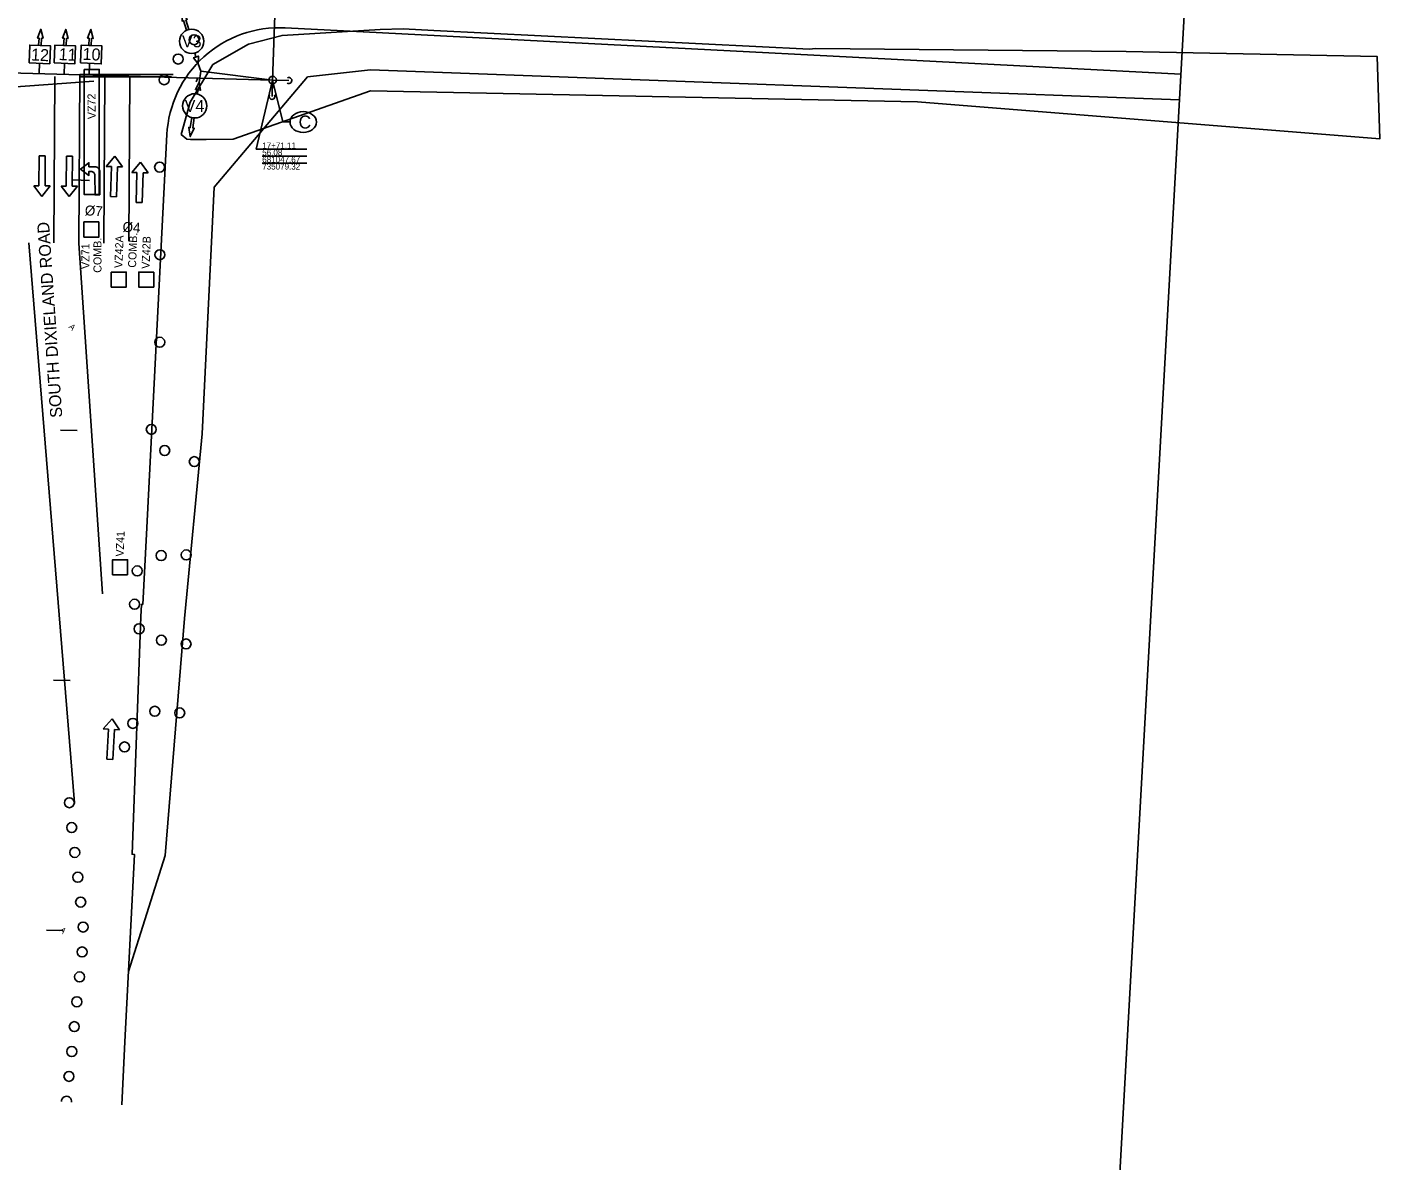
# Model space of a CAD drawing. Extents: x 679444 to 687671, y 733868 to 736107.
# Drawn here: x 680949 to 681490, y 734647 to 735101 of the extents above; entities that cross this region are included whole.
import ezdxf

# ---------------------------------------------------------------- set-up
doc = ezdxf.new("R2010")
doc.units = 0
for name, color, linetype in [('$', 7, 'Continuous'), ('090338 Base_Design base 1-1 - R_Horz Alg', 7, 'Continuous'), ('border All Plan 20-40_Border 1 - Level 1', 7, 'Continuous'), ('Clipping Boundary', 7, 'Continuous'), ('MOT Stage 1', 7, 'Continuous'), ('MOT Stage 1 Lanes', 7, 'Continuous'), ('R_Horz Alg Annot', 7, 'Continuous'), ('R_Horz Alg Station', 7, 'Continuous'), ('RW-EX', 7, 'Continuous'), ('RW-PR', 7, 'Continuous'), ('SIGNAL-EX', 7, 'Continuous'), ('SIGNAL-PLAN VIEW LABLES', 7, 'Continuous'), ('TITEXT', 7, 'Continuous'), ('Video-Zones-pr', 7, 'Continuous')]:
    doc.layers.add(name, color=color, linetype=linetype)

# ---------------------------------------------------------------- blocks, each defined once
blk = doc.blocks.new('BAREL_1514')
at = {"layer": 'MOT Stage 1'}
blk.add_circle((-0.01, 0), 2, dxfattribs=at)
blk = doc.blocks.new('BAREL_1515')
at = {"layer": 'MOT Stage 1'}
blk.add_circle((-0.01, 0), 2, dxfattribs=at)
blk = doc.blocks.new('BAREL_1516')
at = {"layer": 'MOT Stage 1'}
blk.add_circle((-0.01, 0), 2, dxfattribs=at)
blk = doc.blocks.new('BAREL_1517')
at = {"layer": 'MOT Stage 1'}
blk.add_circle((-0.01, 0), 2, dxfattribs=at)
blk = doc.blocks.new('BAREL_1518')
at = {"layer": 'MOT Stage 1'}
blk.add_circle((-0.01, 0), 2, dxfattribs=at)
blk = doc.blocks.new('BAREL_1520')
at = {"layer": 'MOT Stage 1'}
blk.add_circle((0, -0.01), 2, dxfattribs=at)
blk = doc.blocks.new('BAREL_1521')
at = {"layer": 'MOT Stage 1'}
blk.add_circle((0, -0.01), 2, dxfattribs=at)
blk = doc.blocks.new('BAREL_1522')
at = {"layer": 'MOT Stage 1'}
blk.add_circle((0, -0.01), 2, dxfattribs=at)
blk = doc.blocks.new('BAREL_1523')
at = {"layer": 'MOT Stage 1'}
blk.add_circle((0, -0.01), 2, dxfattribs=at)
blk = doc.blocks.new('SARROW_172')
at = {"layer": 'MOT Stage 1'}
for p, q in [((0, 0), (-6, 0)), ((0, -29.4), (0, 0)), ((-6, -29.4), (-6, 0)), ((-6, -29.4), (-11, -29.4)), ((-3, -39.8), (-11, -29.4)), ((5, -29.4), (-3, -39.8)), ((5, -29.4), (0, -29.4))]:
    blk.add_line(p, q, dxfattribs=at)
blk = doc.blocks.new('SARROW_177')
at = {"layer": 'MOT Stage 1'}
for p, q in [((0, 0), (-6, 0)), ((0, -29.4), (0, 0)), ((-6, -29.4), (-6, 0)), ((-6, -29.4), (-11, -29.4)), ((-3, -39.8), (-11, -29.4)), ((5, -29.4), (-3, -39.8)), ((5, -29.4), (0, -29.4))]:
    blk.add_line(p, q, dxfattribs=at)
blk = doc.blocks.new('SARROW_182')
at = {"layer": 'MOT Stage 1'}
for p, q in [((0, 0), (-6, 0)), ((0, -29.4), (0, 0)), ((-6, -29.4), (-6, 0)), ((-6, -29.4), (-11, -29.4)), ((-3, -39.8), (-11, -29.4)), ((5, -29.4), (-3, -39.8)), ((5, -29.4), (0, -29.4))]:
    blk.add_line(p, q, dxfattribs=at)
blk = doc.blocks.new('BAREL_1564')
at = {"layer": 'MOT Stage 1'}
blk.add_circle((0, -0.01), 2, dxfattribs=at)
blk = doc.blocks.new('BAREL_1565')
at = {"layer": 'MOT Stage 1'}
blk.add_circle((0, -0.01), 2, dxfattribs=at)
blk = doc.blocks.new('BAREL_1566')
at = {"layer": 'MOT Stage 1'}
blk.add_circle((0, -0.01), 2, dxfattribs=at)
blk = doc.blocks.new('BAREL_1567')
at = {"layer": 'MOT Stage 1'}
blk.add_circle((0, -0.01), 2, dxfattribs=at)
blk = doc.blocks.new('BAREL_1568')
at = {"layer": 'MOT Stage 1'}
blk.add_circle((-0.01, 0), 2, dxfattribs=at)
blk = doc.blocks.new('BAREL_1569')
at = {"layer": 'MOT Stage 1'}
blk.add_circle((-0.01, 0), 2, dxfattribs=at)
blk = doc.blocks.new('BAREL_1570')
at = {"layer": 'MOT Stage 1'}
blk.add_circle((-0.01, 0), 2, dxfattribs=at)
blk = doc.blocks.new('BAREL_1571')
at = {"layer": 'MOT Stage 1'}
blk.add_circle((-0.01, 0), 2, dxfattribs=at)
blk = doc.blocks.new('BAREL_1572')
at = {"layer": 'MOT Stage 1'}
blk.add_circle((-0.01, 0), 2, dxfattribs=at)
blk = doc.blocks.new('BAREL_1573')
at = {"layer": 'MOT Stage 1'}
blk.add_circle((-0.01, 0), 2, dxfattribs=at)
blk = doc.blocks.new('BAREL_1574')
at = {"layer": 'MOT Stage 1'}
blk.add_circle((-0.01, 0), 2, dxfattribs=at)
blk = doc.blocks.new('SARROW_185')
at = {"layer": 'MOT Stage 1'}
for p, q in [((0, 0), (-6, 0)), ((0, -29.4), (0, 0)), ((-6, -29.4), (-6, 0)), ((-6, -29.4), (-11, -29.4)), ((-3, -39.8), (-11, -29.4)), ((5, -29.4), (-3, -39.8)), ((5, -29.4), (0, -29.4))]:
    blk.add_line(p, q, dxfattribs=at)
blk = doc.blocks.new('BAREL_1583')
at = {"layer": 'MOT Stage 1'}
blk.add_circle((-0.01, 0), 2, dxfattribs=at)
blk = doc.blocks.new('BAREL_1584')
at = {"layer": 'MOT Stage 1'}
blk.add_circle((-0.01, 0), 2, dxfattribs=at)
blk = doc.blocks.new('BAREL_1585')
at = {"layer": 'MOT Stage 1'}
blk.add_circle((-0.01, 0), 2, dxfattribs=at)
blk = doc.blocks.new('BAREL_1586')
at = {"layer": 'MOT Stage 1'}
blk.add_circle((-0.01, 0), 2, dxfattribs=at)
blk = doc.blocks.new('BAREL_1587')
at = {"layer": 'MOT Stage 1'}
blk.add_circle((-0.01, 0), 2, dxfattribs=at)
blk = doc.blocks.new('BAREL_1588')
at = {"layer": 'MOT Stage 1'}
blk.add_circle((-0.01, 0), 2, dxfattribs=at)
blk = doc.blocks.new('BAREL_1589')
at = {"layer": 'MOT Stage 1'}
blk.add_circle((-0.01, 0), 2, dxfattribs=at)
blk = doc.blocks.new('BAREL_1590')
at = {"layer": 'MOT Stage 1'}
blk.add_circle((-0.01, 0), 2, dxfattribs=at)
blk = doc.blocks.new('BAREL_1591')
at = {"layer": 'MOT Stage 1'}
blk.add_circle((-0.01, 0), 2, dxfattribs=at)
blk = doc.blocks.new('BAREL_1592')
at = {"layer": 'MOT Stage 1'}
blk.add_circle((-0.01, 0), 2, dxfattribs=at)
blk = doc.blocks.new('BAREL_1593')
at = {"layer": 'MOT Stage 1'}
blk.add_circle((-0.01, 0), 2, dxfattribs=at)
blk = doc.blocks.new('BAREL_1594')
at = {"layer": 'MOT Stage 1'}
blk.add_circle((-0.01, 0), 2, dxfattribs=at)
blk = doc.blocks.new('SARROW_186')
at = {"layer": 'MOT Stage 1'}
for p, q in [((-6, -29.4), (-6, 0)), ((0, 0), (-6, 0)), ((0, -29.4), (0, 0)), ((-6, -29.4), (-11, -29.4)), ((-3, -39.8), (-11, -29.4)), ((5, -29.4), (-3, -39.8)), ((5, -29.4), (0, -29.4))]:
    blk.add_line(p, q, dxfattribs=at)
blk = doc.blocks.new('POINT_DISPLAY')
blk.add_line((0, 0), (0, 0))

msp = doc.modelspace()

# ---------------------------------------------------------------- linework, layer by layer
at = {"layer": '$'}
for p, q in [((681051.82, 735197.81), (681047.67, 735079.32)), ((681047.67, 735079.32), (680910.95, 735083.16))]:
    msp.add_line(p, q, dxfattribs=at)
for points in [[(681047.44, 735072.83), (681047.67, 735079.32)], [(681054.16, 735079.14), (681047.67, 735079.32)]]:
    msp.add_lwpolyline(points, dxfattribs=at)
for centre, start, end in [((681054.16, 735079.14), 238.3918, 118.3918), ((681047.44, 735072.83), 147.9937, 27.9937)]:
    msp.add_arc(centre, 1.2, start, end, dxfattribs=at)
at = {"layer": 'border All Plan 20-40_Border 1 - Level 1'}
msp.add_line((681384.1, 734599.57), (681440.93, 735625.3), dxfattribs=at)
at = {"layer": 'Clipping Boundary'}
msp.add_lwpolyline([(681013.37, 735055.78), (681014.86, 735055.61), (681021.06, 735055.55), (681031.94, 735055.66), (681086.85, 735075.03), (681305.56, 735070.63), (681490.46, 735055.86), (681489.41, 735088.76), (681389.02, 735090.81), (681264.81, 735091.94), (681262.37, 735091.76), (681112.19, 735099.16), (681099.83, 735099.77), (681090.68, 735099.5), (681051.46, 735097.19), (681038, 735093.68), (681023.75, 735085.5), (681014.67, 735070.5), (681011.14, 735057.59)], close=True, dxfattribs=at)
at = {"layer": 'MOT Stage 1'}
for points in [[(680976.62, 735044.72), (680976.94, 735044.72), (680974.21, 735044.7), (680974.2, 735046.29), (680970.92, 735043.73), (680974.23, 735041.21), (680974.22, 735042.8), (680975.05, 735042.81)], [(680976.65, 735041.23), (680976.7, 735033.43), (680978.61, 735033.45)], [(680978.61, 735033.45), (680978.54, 735043.15), (680978.54, 735042.83)]]:
    msp.add_lwpolyline(points, dxfattribs=at)
for centre, radius, start, end in [((680975.06, 735041.22), 1.59, 0.3996, 90.3996), ((680976.64, 735042.82), 1.9, 0.3996, 90.3996), ((680965.25, 734671.07), 2, 349.7483, 183.9093)]:
    msp.add_arc(centre, radius, start, end, dxfattribs=at)
at = {"layer": 'MOT Stage 1 Lanes'}
for p, q in [((680950.15, 735014.32), (680968.4, 734790.33)), ((680979.71, 734873.94), (680970.15, 735014.19))]:
    msp.add_line(p, q, dxfattribs=at)
for points in [[(680960.15, 735014.25), (680960.6, 735080.81)], [(680970.15, 735014.19), (680970.61, 735081.6), (681007.85, 735081.6)], [(680970.6, 735080.6), (681007.28, 735080.6)], [(680980.15, 735014.12), (680980.6, 735080.67)], [(680990.16, 735014.99), (680990.6, 735080.6)]]:
    msp.add_lwpolyline(points, dxfattribs=at)
at = {"layer": 'R_Horz Alg Annot'}
for p, q in [((681043.54, 735051.78), (681061.35, 735051.78)), ((681043.54, 735048.98), (681061.35, 735048.98)), ((681043.54, 735046.18), (681061.35, 735046.18))]:
    msp.add_line(p, q, dxfattribs=at)
msp.add_lwpolyline([(681047.67, 735079.32), (681041.14, 735051.78), (681043.54, 735051.78)], dxfattribs=at)
at = {"layer": 'R_Horz Alg Station'}
for points in [[(680967.77, 735039.47), (680974.43, 735039.13)], [(680962.88, 734939.44), (680969.54, 734939.26)], [(680960.07, 734839.48), (680966.73, 734839.29)], [(680957.26, 734739.52), (680963.92, 734739.33)]]:
    msp.add_lwpolyline(points, dxfattribs=at)
at = {"layer": 'RW-EX'}
for p, q in [((681091.59, 735098.17), (681052.68, 735100.18)), ((681091.59, 735098.17), (681410.81, 735081.67)), ((680997.23, 734897.78), (681005.41, 735057.54)), ((680995.79, 734869.71), (680997.23, 734897.78))]:
    msp.add_line(p, q, dxfattribs=at)
msp.add_lwpolyline([(680987.37, 734669.6), (680988.64, 734694.88), (680992.39, 734769.78), (680991.5, 734769.81), (680995.01, 734864.75), (680995.19, 734869.73), (680995.79, 734869.71)], dxfattribs=at)
msp.add_arc((681050.35, 735055.24), 45, 87.0415, 177.0663, dxfattribs=at)
at = {"layer": 'RW-PR'}
for p, q in [((681061.65, 735080.69), (681086.82, 735083.39)), ((681024.36, 735036.57), (681061.65, 735080.69)), ((681024.36, 735036.57), (681019.52, 734937.85))]:
    msp.add_line(p, q, dxfattribs=at)
for points in [[(681086.82, 735083.39), (681410.25, 735071.44)], [(680990.05, 734722.92), (681004.78, 734769.38), (681012.45, 734864.05), (681019.52, 734937.85)]]:
    msp.add_lwpolyline(points, dxfattribs=at)
at = {"layer": 'SIGNAL-EX'}
msp.add_lwpolyline([(680943.31, 735076.55), (680976.18, 735078.85)], dxfattribs=at)
at = {"layer": 'SIGNAL-PLAN VIEW LABLES'}
for p, q in [((680954.97, 735099.63), (680953.68, 735096.15)), ((680955.89, 735096.03), (680954.97, 735099.63)), ((680964.97, 735099.6), (680963.68, 735096.13)), ((680965.89, 735096.01), (680964.97, 735099.6)), ((680975, 735099.59), (680973.71, 735096.11)), ((680975.93, 735096), (680975, 735099.59)), ((680953.68, 735096.15), (680954.28, 735096.12)), ((680954.28, 735096.12), (680954.13, 735093.23)), ((680955.14, 735093.2), (680955.29, 735096.06)), ((680955.29, 735096.06), (680955.89, 735096.03)), ((680963.68, 735096.13), (680964.28, 735096.09)), ((680964.28, 735096.09), (680964.13, 735093.21)), ((680965.14, 735093.17), (680965.29, 735096.04)), ((680965.29, 735096.04), (680965.89, 735096.01)), ((680973.71, 735096.11), (680974.32, 735096.08)), ((680974.32, 735096.08), (680974.17, 735093.2)), ((680975.18, 735093.16), (680975.32, 735096.03)), ((680975.32, 735096.03), (680975.93, 735096)), ((680954.13, 735093.23), (680955.14, 735093.2)), ((680964.13, 735093.21), (680965.14, 735093.17)), ((680974.17, 735093.2), (680975.18, 735093.16)), ((681018.26, 735078.33), (681018.93, 735082.88)), ((681017.58, 735073.77), (681017.82, 735075.4))]:
    msp.add_line(p, q, dxfattribs=at)
for points in [[(681013, 735103.4), (681013.58, 735103.58), (681011.43, 735106.61), (681011.47, 735102.9), (681012.04, 735103.09), (681013.28, 735099.25), (681014.24, 735099.56), (681013, 735103.4)], [(681014.24, 735099.56), (681013, 735103.4), (681013.58, 735103.58), (681011.43, 735106.61), (681011.47, 735102.9), (681012.04, 735103.09), (681013.28, 735099.25)], [(680955.14, 735093.2), (680955.29, 735096.06), (680955.89, 735096.03), (680954.97, 735099.63), (680953.68, 735096.15), (680954.28, 735096.12), (680954.13, 735093.23)], [(680965.14, 735093.17), (680965.29, 735096.04), (680965.89, 735096.01), (680964.97, 735099.6), (680963.68, 735096.13), (680964.28, 735096.09), (680964.13, 735093.21)], [(680975.18, 735093.16), (680975.32, 735096.03), (680975.93, 735096), (680975, 735099.59), (680973.71, 735096.11), (680974.32, 735096.08), (680974.17, 735093.2)], [(681017.04, 735088.58), (681016.52, 735090.14)], [(680954.28, 735081.94), (680954.44, 735086.05)], [(680964.27, 735081.66), (680964.44, 735086.02)], [(680974.27, 735081.38), (680974.45, 735085.99)], [(681018.93, 735082.88), (681017.97, 735085.77)], [(681018.93, 735082.88), (681047.67, 735079.32)], [(681017.73, 735080.18), (681017.07, 735078.67)], [(681047.67, 735079.32), (681051.8, 735062.61), (681054.66, 735062.61)], [(681014.77, 735060.35), (681014.17, 735060.44), (681014.73, 735056.77), (681016.37, 735060.1), (681015.77, 735060.19), (681016.38, 735064.18), (681015.39, 735064.33), (681014.77, 735060.35)], [(681015.39, 735064.33), (681014.77, 735060.35), (681014.17, 735060.44), (681014.73, 735056.77), (681016.37, 735060.1), (681015.77, 735060.19), (681016.38, 735064.18)]]:
    msp.add_lwpolyline(points, dxfattribs=at)
for points in [[(680950.31, 735086.22), (680950.56, 735093.36), (680958.82, 735093.07), (680958.57, 735085.87)], [(680960.35, 735086.2), (680960.6, 735093.33), (680968.86, 735093.05), (680968.61, 735085.85)], [(680970.91, 735086.17), (680971.16, 735093.3), (680979.41, 735093.02), (680979.16, 735085.82)], [(681017.97, 735085.77), (681016.05, 735088.26), (681018.03, 735088.9)], [(681018.26, 735078.33), (681018.85, 735075.24), (681016.8, 735075.56)]]:
    msp.add_lwpolyline(points, close=True, dxfattribs=at)
for centre, radius in [((681015.33, 735094.84), 4.85), ((681047.67, 735079.32), 1.5), ((681016.54, 735069.03), 4.85)]:
    msp.add_circle(centre, radius, dxfattribs=at)
msp.add_ellipse((681059.92, 735062.56), major_axis=(-5.27, 0), ratio=0.790685, dxfattribs=at)
at = {"layer": 'Video-Zones-pr'}
msp.add_lwpolyline([(680972.34, 735083.6), (680972.29, 735033.6), (680978.29, 735033.6), (680978.34, 735083.6)], close=True, dxfattribs=at)
for points in [[(680978.25, 735022.6), (680978.25, 735016.6), (680972.25, 735016.6), (680972.25, 735022.6), (680978.25, 735022.6)], [(680983.15, 735002.6), (680983.15, 734996.6), (680989.15, 734996.6), (680989.15, 735002.6), (680983.15, 735002.6)], [(681000.15, 735002.6), (681000.15, 734996.6), (680994.15, 734996.6), (680994.15, 735002.6), (681000.15, 735002.6)], [(680989.66, 734881.6), (680983.66, 734881.6), (680983.66, 734887.6), (680989.66, 734887.6), (680989.66, 734881.6)]]:
    msp.add_lwpolyline(points, dxfattribs=at)

# ---------------------------------------------------------------- block references
at = {"layer": '$', "rotation": 87.9936667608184}
msp.add_blockref('POINT_DISPLAY', (681047.51, 735074.83), dxfattribs=at)
at = {"layer": 'MOT Stage 1'}
for name, p in [('BAREL_1574', (681016.28, 735095.49)), ('BAREL_1573', (681009.94, 735087.76)), ('BAREL_1572', (681004.33, 735079.48)), ('BAREL_1571', (681002.52, 735044.53)), ('BAREL_1570', (681002.61, 735009.53)), ('BAREL_1569', (681002.57, 734974.53)), ('BAREL_1568', (680999.19, 734939.69)), ('BAREL_1514', (681004.53, 734931.24)), ('BAREL_1515', (681016.39, 734926.8)), ('BAREL_1517', (681003.14, 734889.23)), ('BAREL_1516', (681013.14, 734889.49)), ('BAREL_1518', (680993.55, 734883.12)), ('BAREL_1565', (680992.49, 734869.8)), ('BAREL_1564', (680994.29, 734859.96)), ('BAREL_1520', (681003.19, 734855.4)), ('BAREL_1521', (681013.07, 734853.91)), ('BAREL_1522', (681000.55, 734826.98)), ('BAREL_1566', (680991.79, 734822.17)), ('BAREL_1523', (681010.53, 734826.35)), ('BAREL_1567', (680988.5, 734812.72)), ('BAREL_1594', (680966.41, 734790.43)), ('BAREL_1593', (680967.35, 734780.48)), ('BAREL_1592', (680968.59, 734770.55)), ('BAREL_1591', (680969.8, 734760.63)), ('BAREL_1590', (680970.94, 734750.69)), ('BAREL_1589', (680971.9, 734740.74)), ('BAREL_1588', (680971.5, 734730.75)), ('BAREL_1587', (680970.49, 734720.8)), ('BAREL_1586', (680969.42, 734710.86)), ('BAREL_1585', (680968.4, 734700.91)), ('BAREL_1584', (680967.39, 734690.96)), ('BAREL_1583', (680966.27, 734681.02))]:
    msp.add_blockref(name, p, dxfattribs=at)
for name, p, xscale, yscale, rotation in [('SARROW_172', (680956.78, 735049.01), 0.4075873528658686, 0.4075873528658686, -0.42203112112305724), ('SARROW_177', (680967.68, 735048.94), 0.4075873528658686, 0.4075873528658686, -0.42203112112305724), ('SARROW_186', (680982.82, 735032.79), 0.4075873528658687, 0.40758735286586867, 178.17728500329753), ('SARROW_182', (680993.07, 735030.41), 0.4075873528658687, 0.40758735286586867, 178.17728500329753), ('SARROW_185', (680981.39, 734807.87), 0.4075873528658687, 0.40758735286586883, 176.95379060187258)]:
    msp.add_blockref(name, p, dxfattribs=dict(at, xscale=xscale, yscale=yscale, rotation=rotation))

# ---------------------------------------------------------------- texts
at = {"layer": '$'}
for s, height, rotation, p in [('VZ72', 3.2, 90.6151, (680976.95, 735063.74)), ('SOUTH DIXIELAND ROAD', 4.8, 93.8995, (680963.61, 734944.51)), ('COMB.', 3.2, 87.7397, (680993.04, 735004.26)), ('VZ71', 3.2, 90, (680974.45, 735003.81)), ('COMB.', 3.2, 90, (680979.25, 735002.29)), ('VZ42A', 3.2, 87.7397, (680987.59, 735004.11)), ('VZ42B', 3.2, 87.7397, (680998.46, 735003.8)), ('VZ41', 3.2, 87.4181, (680988.08, 734888.76))]:
    msp.add_text(s, height=height, rotation=rotation, dxfattribs=at).set_placement(p)
at = {"layer": '090338 Base_Design base 1-1 - R_Horz Alg'}
for p in [(680965.98, 734980.49), (680962.23, 734739.27)]:
    msp.add_text('A', height=2.4, rotation=315.2103, dxfattribs=at).set_placement(p)
at = {"layer": 'R_Horz Alg Annot'}
for s, p in [('56.08', (681043.54, 735049.18)), ('17+71.11', (681043.54, 735051.98)), ('681047.67', (681043.54, 735046.38)), ('735079.32', (681043.54, 735043.58))]:
    msp.add_text(s, height=2.4, dxfattribs=at).set_placement(p)
at = {"layer": 'SIGNAL-PLAN VIEW LABLES'}
for s, height, p in [('V3', 4.8, (681011.44, 735092.44)), ('V4', 4.8, (681012.54, 735066.63)), ('C', 5.2, (681058.06, 735059.96))]:
    msp.add_text(s, height=height, dxfattribs=at).set_placement(p)
for s, p in [('12', (680951, 735087.21)), ('11', (680962.07, 735087.36)), ('10', (680971.6, 735087.46))]:
    msp.add_text(s, height=4.8, rotation=357.0414, dxfattribs=at).set_placement(p)
at = {"layer": 'TITEXT'}
for s, p in [('%%C7', (680972.49, 735025.3)), ('%%C4', (680987.58, 735018.72))]:
    msp.add_text(s, height=4, rotation=356.2723, dxfattribs=at).set_placement(p)

doc.saveas('drawing.dxf')
